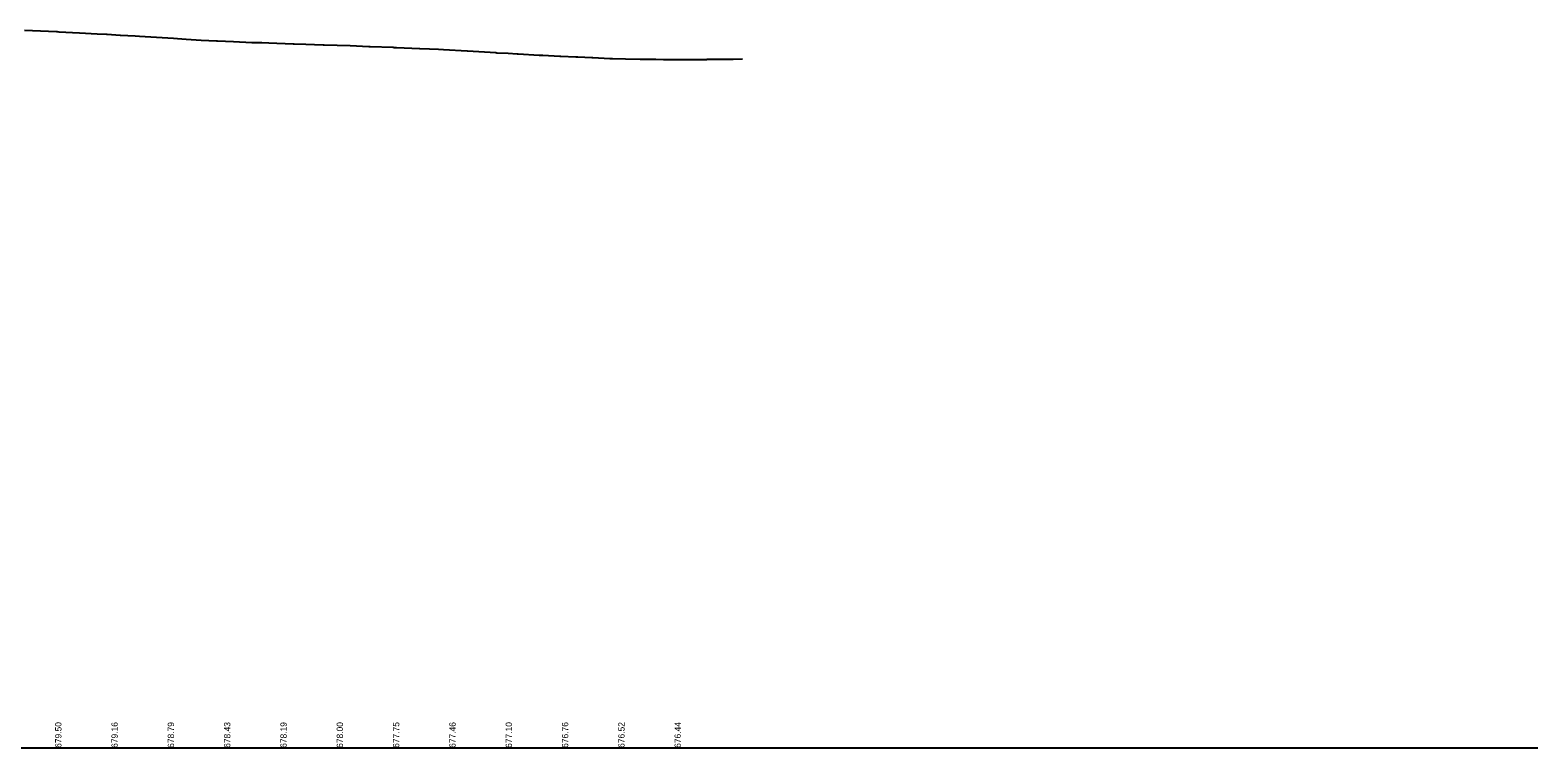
# Model space of a CAD drawing. Extents: x 153902 to 157473, y 413085 to 414252.
# Drawn here: x 156804 to 157473, y 413545 to 413864 of the extents above; entities that cross this region are included whole.
import ezdxf

# ---------------------------------------------------------------- set-up
doc = ezdxf.new("R2010")
doc.units = 0
for name, color, linetype in [('GE_P_Alignment', 7, 'Continuous'), ('HY_X_Water_Edge', 7, 'Continuous'), ('RW_X_Esmt_SH', 7, 'Continuous')]:
    doc.layers.add(name, color=color, linetype=linetype)

msp = doc.modelspace()

# ---------------------------------------------------------------- linework, layer by layer
at = {"layer": 'GE_P_Alignment'}
msp.add_line((156117.51, 413544.82), (157473.02, 413544.82), dxfattribs=at)
at = {"layer": 'RW_X_Esmt_SH'}
msp.add_lwpolyline([(156801.11, 413863.58), (156815.27, 413862.93), (156815.59, 413862.92), (156816.4, 413862.88), (156825.46, 413862.41), (156833.34, 413862), (156837.55, 413861.76), (156837.78, 413861.75), (156843.63, 413861.39), (156843.79, 413861.38), (156850.28, 413861.03), (156852.21, 413860.91), (156862.26, 413860.28), (156862.29, 413860.28), (156867.22, 413859.99), (156868.97, 413859.88), (156872.91, 413859.62), (156879.57, 413859.17), (156886.34, 413858.83), (156886.49, 413858.82), (156886.83, 413858.81), (156893.88, 413858.49), (156902.05, 413858.14), (156902.62, 413858.12), (156906.44, 413858.03), (156909.65, 413857.92), (156920.34, 413857.48), (156920.8, 413857.47), (156926.06, 413857.34), (156933.65, 413857.12), (156934.16, 413857.1), (156945.67, 413856.7), (156953.98, 413856.36), (156954.26, 413856.35), (156954.52, 413856.34), (156964.72, 413855.95), (156965.28, 413855.93), (156966.28, 413855.89), (156976.53, 413855.43), (156976.68, 413855.42), (156980.96, 413855.24), (156984.89, 413855.07), (156987.07, 413854.96), (156987.12, 413854.96), (156997.58, 413854.35), (156997.84, 413854.34), (157000.36, 413854.2), (157010.35, 413853.59), (157010.74, 413853.57), (157015.83, 413853.3), (157019.81, 413853.07), (157020.25, 413853.04), (157029.68, 413852.54), (157030.5, 413852.49), (157031.3, 413852.45), (157038.73, 413852.02), (157039.28, 413851.99), (157045.93, 413851.73), (157046.77, 413851.69), (157053.06, 413851.42), (157053.45, 413851.39), (157061.03, 413851.04), (157061.4, 413851.02), (157062.24, 413851), (157067.93, 413850.89), (157074.48, 413850.74), (157074.55, 413850.73), (157077.71, 413850.68), (157081.37, 413850.62), (157084.81, 413850.55), (157084.9, 413850.55), (157091.11, 413850.57), (157091.34, 413850.57), (157097.39, 413850.55), (157103.89, 413850.61), (157104.16, 413850.62), (157112.47, 413850.69), (157112.54, 413850.69), (157115.7, 413850.73), (157119.89, 413850.77)], dxfattribs=at)

# ---------------------------------------------------------------- texts
at = {"layer": 'HY_X_Water_Edge'}
for s, p in [('679.50', (156817.51, 413544.82)), ('679.16', (156842.51, 413544.82)), ('678.79', (156867.51, 413544.82)), ('678.43', (156892.51, 413544.82)), ('678.19', (156917.51, 413544.82)), ('678.00', (156942.51, 413544.82)), ('677.75', (156967.51, 413544.82)), ('677.46', (156992.51, 413544.82)), ('677.10', (157017.51, 413544.82)), ('676.76', (157042.51, 413544.82)), ('676.52', (157067.51, 413544.82)), ('676.44', (157092.51, 413544.82))]:
    msp.add_text(s, height=2.8, rotation=90, dxfattribs=at).set_placement(p)

doc.saveas('drawing.dxf')
